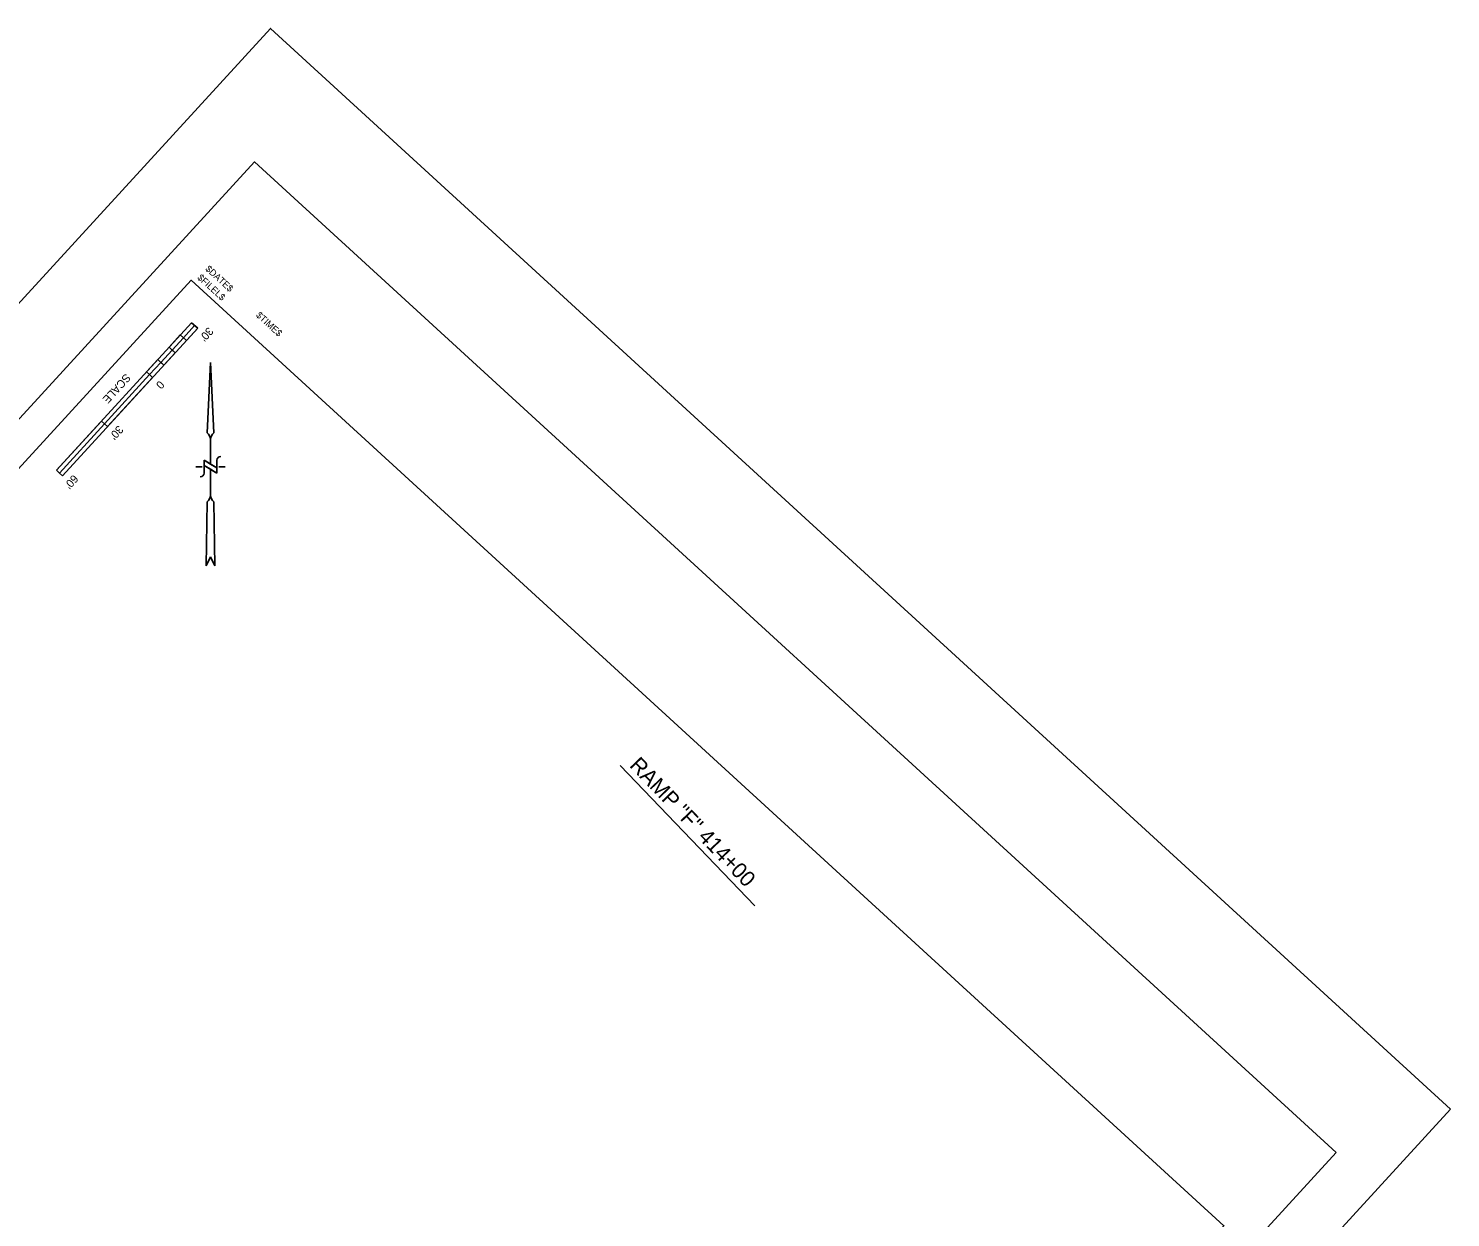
# Model space of a CAD drawing. Extents: x 2149167 to 2150427, y 142619 to 143901.
# Drawn here: x 2149787 to 2150427, y 143366 to 143901 of the extents above; entities that cross this region are included whole.
import ezdxf

# ---------------------------------------------------------------- set-up
doc = ezdxf.new("R2010")
doc.units = 0
for name, color, linetype in [('SHT_Match_Lines', 7, 'Continuous'), ('SHT_North_Arrow', 7, 'Continuous'), ('SHT_Plot_Shape_Half', 7, 'Continuous'), ('SHT_Scale', 7, 'Continuous'), ('SHT_Sheet_Border', 7, 'Continuous'), ('TOPO_Curb Back', 7, 'Continuous'), ('TOPO_Curb Gut', 7, 'Continuous'), ('TOPO_Power Anchor', 7, 'Continuous')]:
    doc.layers.add(name, color=color, linetype=linetype)

msp = doc.modelspace()

# ---------------------------------------------------------------- linework, layer by layer
at = {"layer": 'SHT_Match_Lines'}
msp.add_line((2150114.26, 143506.48), (2150053.65, 143569.73), dxfattribs=at)
at = {"layer": 'SHT_North_Arrow'}
for p, q in [((2149867.84, 143719.31), (2149869.28, 143751.04)), ((2149869.28, 143751.04), (2149867.84, 143719.31)), ((2149869.28, 143751.04), (2149870.72, 143719.31)), ((2149870.72, 143719.31), (2149869.28, 143751.04)), ((2149869.28, 143705.27), (2149869.28, 143716.5)), ((2149872.16, 143703.55), (2149866.4, 143707)), ((2149866.4, 143707), (2149872.16, 143703.55)), ((2149866.4, 143707), (2149866.4, 143701.24)), ((2149869.28, 143705.27), (2149866.4, 143707)), ((2149866.4, 143707), (2149866.4, 143704.7)), ((2149872.16, 143703.55), (2149869.28, 143705.27)), ((2149872.16, 143707), (2149872.16, 143701.24)), ((2149865.54, 143704.12), (2149862.66, 143704.12)), ((2149872.16, 143701.24), (2149866.4, 143704.7)), ((2149869.28, 143691.17), (2149869.28, 143702.97)), ((2149872.16, 143701.24), (2149872.16, 143703.55)), ((2149875.9, 143704.12), (2149873.02, 143704.12)), ((2149867.26, 143659.51), (2149867.84, 143688.29)), ((2149867.84, 143688.29), (2149867.26, 143659.51)), ((2149871.29, 143659.51), (2149870.72, 143688.29)), ((2149871.29, 143659.51), (2149870.72, 143688.29)), ((2149867.26, 143659.51), (2149869.28, 143663.54)), ((2149867.26, 143659.51), (2149869.28, 143663.54)), ((2149869.28, 143663.54), (2149871.29, 143659.51)), ((2149869.28, 143663.54), (2149871.29, 143659.51))]:
    msp.add_line(p, q, dxfattribs=at)
for points in [[(2149866.4, 143704.7), (2149869.28, 143702.97), (2149872.16, 143701.24)], [(2149869.28, 143691.17), (2149869.28, 143691.17), (2149869.28, 143691.17)]]:
    msp.add_lwpolyline(points, dxfattribs=at)
for centre, radius, start, end in [((2149865.83, 143716.5), 3.45, 0, 54.38016), ((2149865.83, 143716.5), 3.45, 0, 54.38016), ((2149872.73, 143716.5), 3.45, 125.61984, 180), ((2149872.73, 143716.5), 3.45, 125.61984, 180), ((2149873.89, 143707), 1.73, 90, 180), ((2149864.67, 143701.24), 1.73, 270, 0), ((2149864.27, 143691.87), 5.06, 314.95671, 352.41889), ((2149864.27, 143691.87), 5.06, 314.95671, 352.059), ((2149874.29, 143691.87), 5.06, 187.58111, 225.04329), ((2149874.29, 143691.87), 5.06, 187.941, 225.04329)]:
    msp.add_arc(centre, radius, start, end, dxfattribs=at)
at = {"layer": 'SHT_Plot_Shape_Half'}
msp.add_lwpolyline([(2150375.82, 143395.55), (2149686.97, 142643.3), (2149200.22, 143089.02), (2149889.06, 143841.28)], close=True, dxfattribs=at)
at = {"layer": 'SHT_Scale'}
for p, q in [((2149860.75, 143768.92), (2149799.97, 143702.55)), ((2149863.51, 143766.39), (2149802.73, 143700.02)), ((2149855.68, 143763.39), (2149850.62, 143757.86)), ((2149858.45, 143760.86), (2149855.68, 143763.39)), ((2149857.06, 143762.13), (2149855.68, 143763.39)), ((2149862.13, 143767.66), (2149857.06, 143762.13)), ((2149862.13, 143767.66), (2149857.06, 143762.13)), ((2149858.45, 143760.86), (2149863.51, 143766.39)), ((2149863.51, 143766.39), (2149860.75, 143768.92)), ((2149863.51, 143766.39), (2149862.13, 143767.66)), ((2149852, 143756.6), (2149846.93, 143751.06)), ((2149852, 143756.6), (2149846.93, 143751.06)), ((2149853.38, 143755.33), (2149850.62, 143757.86)), ((2149853.38, 143755.33), (2149850.62, 143757.86)), ((2149850.62, 143757.86), (2149852, 143756.6)), ((2149857.06, 143762.13), (2149852, 143756.6)), ((2149852, 143756.6), (2149857.06, 143762.13)), ((2149853.38, 143755.33), (2149852, 143756.6)), ((2149857.06, 143762.13), (2149858.45, 143760.86)), ((2149845.55, 143752.33), (2149840.49, 143746.8)), ((2149846.93, 143751.06), (2149841.87, 143745.53)), ((2149841.87, 143745.53), (2149846.93, 143751.06)), ((2149848.32, 143749.8), (2149845.55, 143752.33)), ((2149846.93, 143751.06), (2149845.55, 143752.33)), ((2149846.93, 143751.06), (2149848.32, 143749.8)), ((2149848.32, 143749.8), (2149853.38, 143755.33)), ((2149841.87, 143745.53), (2149801.35, 143701.28)), ((2149841.87, 143745.53), (2149821.61, 143723.41)), ((2149822.99, 143722.14), (2149843.25, 143744.27)), ((2149840.49, 143746.8), (2149841.87, 143745.53)), ((2149840.49, 143746.8), (2149841.87, 143745.53)), ((2149841.87, 143745.53), (2149843.25, 143744.27)), ((2149843.25, 143744.27), (2149841.87, 143745.53)), ((2149820.23, 143724.67), (2149799.97, 143702.55)), ((2149820.23, 143724.67), (2149821.61, 143723.41)), ((2149821.61, 143723.41), (2149820.23, 143724.67)), ((2149801.35, 143701.28), (2149821.61, 143723.41)), ((2149821.61, 143723.41), (2149822.99, 143722.14)), ((2149821.61, 143723.41), (2149822.99, 143722.14)), ((2149801.35, 143701.28), (2149799.97, 143702.55)), ((2149799.97, 143702.55), (2149801.35, 143701.28)), ((2149802.73, 143700.02), (2149801.35, 143701.28))]:
    msp.add_line(p, q, dxfattribs=at)
at = {"layer": 'SHT_Sheet_Border'}
msp.add_lwpolyline([(2149222.42, 143091.06), (2149860.62, 143788), (2150325.25, 143362.54), (2149687.05, 142665.6)], close=True, dxfattribs=at)
at = {"layer": 'TOPO_Curb Gut'}
msp.add_lwpolyline([(2150427.25, 143415.07), (2149697.88, 142618.56), (2149166.87, 143104.81), (2149896.24, 143901.31)], close=True, dxfattribs=at)

# ---------------------------------------------------------------- texts
at = {"layer": 'SHT_Scale'}
for s, p in [("30'", (2149868.3, 143767.18)), ('SCALE', (2149831.07, 143746.28)), ('0', (2149846.26, 143743.11)), ("30'", (2149827.78, 143722.93)), ("60'", (2149807.52, 143700.8))]:
    msp.add_text(s, height=3.6, rotation=227.51948, dxfattribs=at).set_placement(p)
at = {"layer": 'TOPO_Curb Back'}
for s, p in [('$FILEL$', (2149863.12, 143788.85)), ('$DATE$', (2149866.72, 143792.78)), ('$TIME$', (2149889.51, 143771.92))]:
    msp.add_text(s, height=3, rotation=317.51948, dxfattribs=at).set_placement(p)
at = {"layer": 'TOPO_Power Anchor'}
msp.add_text('RAMP "F" 414+00', height=7, rotation=313.81741, dxfattribs=at).set_placement((2150057.42, 143569.35))

doc.saveas('drawing.dxf')
